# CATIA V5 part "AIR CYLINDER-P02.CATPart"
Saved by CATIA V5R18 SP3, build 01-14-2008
Part number: Air Cylinder Part
Bounding box of the stored display mesh (mm): x -310.9 to -0.6, y -26.998 to 26.998, z -26.998 to 26.998
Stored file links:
  E:\#00 CATIA V5 Movie\#03 CATIA V5 Data\#07 KIN\Balance Unit (1)\AIR CYLINDER-P02.CATPart
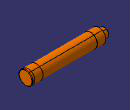
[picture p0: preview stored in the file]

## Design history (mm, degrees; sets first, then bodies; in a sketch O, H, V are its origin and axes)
Body1 (main body)
  Sketch1 on zx-plane, origin (0, 0, 0), H (-1, 0, 0), V (0, 0, 1)
    line L1 (256.6, 26.5) -> (42.6, 26.5)
    line L2 (42.6, 27) -> (42.6, 26.5)
    line L3 (42.6, 27) -> (9.6, 27)
    line L4 (9.6, 27) -> (2.4, 27)
    arc A1 centre (2.4, 25.2) radius 1.8 from (2.4, 27) to (0.6, 25.2) ccw
    line L5 (0.6, 0) -> (0.6, 25.2)
    line L6 (310.9, 16.5) -> (310.9, 8.25)
    line L7 (310.9, 16.5) -> (310.4, 17)
    line L8 (289.6, 27) -> (256.6, 27)
    line L9 (256.6, 27) -> (256.6, 26.5)
    line L10 (289.6, 27) -> (289.6, 17.5)
    line L11 (293.6, 17.5) -> (289.6, 17.5)
    line L12 (294.1, 17) -> (293.6, 17.5)
    line L13 (310.4, 17) -> (294.1, 17)
    point P3 (42.6, 27)
    point P4 (42.6, 27)
    point P5 (9.6, 27)
    point P6 (9.6, 27)
    point P7 (2.4, 27)
    point P8 (2.4, 27)
    point P9 (0.6, 25.2)
    point P10 (0.6, 25.2)
    point P11 (310.9, 16.5)
    point P12 (310.9, 16.5)
    point P13 (310.4, 17)
    point P14 (289.6, 27)
    point P15 (256.6, 27)
    point P16 (256.6, 27)
    point P17 (289.6, 27)
    point P18 (293.6, 17.5)
    point P20 (294.1, 17)
    point P21 (293.6, 17.5)
    point P22 (310.4, 17)
    point P23 (294.1, 17)
    point P24 (0.6, 0)
    line L14 (310.9, 8.25) -> (38.8128, 8.25)
    line L15 (38.8128, 8.25) -> (38.8128, 0)
    point P26 (38.8128, 0)
    coincidence: P24 H, P3 P4, P5 P6, P7 P8, P9 P10, P11 P12, P13 P22, P14 P17, P15 P16, P18 P21, P20 P23, P26 H
    horizontal: L14 H
    vertical: L15 V
  Shaft1: profile Sketch1, axis Sketch1.H, angle 360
